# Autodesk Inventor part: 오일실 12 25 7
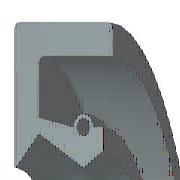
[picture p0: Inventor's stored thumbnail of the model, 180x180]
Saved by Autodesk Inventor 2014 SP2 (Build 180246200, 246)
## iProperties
IsCustomPart: 1
Created: 2012-02
Part Number: 오일실 12 25 7
Material: 고무
Description: 오일-실
Document SubType Name: Modeling
Standard: KS B 2804
Designer: test
Standards Organization: KS
Language: ko-KR
Size Designation: D - 12 25 7
Categories: <MemberInstance><Categories><Category DisplayName="샤프트 부품" InternalName="7f7aeb1f-a693-4053-b835-cee3144e0d98" Mnemonic="SHFT"><Category DisplayName="실링" Intern
Density: 0.93 g/cm^3
Appearance: 고무 - 검은색 - 버전 1.1
Author: test
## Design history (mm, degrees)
revolve "본체" stored, may be unused: angle "d17" = 90 deg
revolve "스프링1" stored, may be unused: angle "d18" = 90 deg
body "Solid1"
sketch "스케치1"
  geometry: L1 (0, 12.5)-(7, 12.5); L2 (7, 10.75)-(1.75, 10.75); L3 (1.75, 7.75)-(4.9, 6); L4 (4.9, 6)-(0, 6); L5 (0, 0)-(9.586, 0) reference; L6 (4.9, 6)-(6.3, 6.875); L7 (0, 18)-(0, -3) reference; L8 (-1.941, 0)-(11.507, 0) reference; L9 (4.2, 8.1)-(1.75, 8.59); L10 (1.75, 8.59)-(1.75, 10.75); L11 (0, 12.5)-(0, 6.088); L12 (4.9, 6)-(0, 6); L13 (1.75, 7.75)-(0.152, 6.028); L14 (7, 12.5)-(7, 10.75); L15 (5.6, 8.1)-(6.3, 8.1); L16 (6.3, 8.1)-(6.3, 6.875); C1 r 0.455 at (4.9, 8.1); A1 r 0.7 centre (4.9, 8.1) between (5.6, 8.1) and (4.2, 8.1); A2 r 0.088 centre (0.088, 6.088) between (0, 6.088) and (0.152, 6.028); 1 further point
  constraints: 28 end point, 5 horizontal alignment, 5 point on line, 4 point on circle, 4 vertical alignment, 3 centre point, 3 tangent, 2 collinear, 2 horizontal, 2 perpendicular, 1 coincident, 1 parallel
  dimensions: "d0" = 25 diameter of L1 L5 (= SD2); "d1" = 1.75 distance of L1.end L2.start (= SD); "d2" = 0.91 diameter of C1 (= SPDI); "d3" = 1.4 diameter of A1 (= SPDA); "d4" = 12 diameter of L3.end L5 (= NND); "d5" = 15.5 diameter of L3.start L5 (= TKDM); "d7" = 17.18 diameter of L9.end L5 (= TKDM + 0.24 x SWDT); "d8" = 1.75 distance between parallel lines of L11 L10 (= SD); "d9" = 4.9 distance from line of L11 C1.centre (= SPDST); "d10" = 16.2 diameter of C1.centre L5 (= HLDM); "d11" = 0.0875 radius of A2 (= 0.25 x LAB); "d12" = 6.3 distance between parallel lines of L11 L16 (= SDI); "d13" = 13.75 diameter of L6.end L5 (= ABDM); "d14" = 7 distance from line of L11 L1.end (= SWDT)
fillet "모깎기1" dims "d6" = 0.3 (= RR)
other parameters: "SD2" = 25 [user parameter; used in 1 equation term], "SWDT" = 7 [user parameter; used in 2 equation terms], "RR" = 0.3 [user parameter; used in 1 equation term], "SD" = 1.75 [user parameter; used in 2 equation terms], "NND" = 12 [user parameter; used in 1 equation term], "SPDA" = 1.4 [user parameter; used in 1 equation term], "SPDI" = 0.91 [user parameter; used in 1 equation term], "TKDM" = 15.5 [user parameter; used in 2 equation terms], "HLDM" = 16.2 [user parameter; used in 1 equation term], "ABDM" = 13.75 [user parameter; used in 1 equation term], "SDI" = 6.3 [user parameter; used in 1 equation term], "SPDST" = 4.9 [user parameter; used in 1 equation term], "LAB" = 0.35 [user parameter; used in 1 equation term], "d15" = 0, "d16" = 0, "d19" = 0
